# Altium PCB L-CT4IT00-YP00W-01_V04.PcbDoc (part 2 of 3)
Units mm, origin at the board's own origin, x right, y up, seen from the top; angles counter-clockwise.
Board outline 45 x 50 mm, 6 copper layers (Top Layer, GND1, Signal3, Siganl4, GND5, Bottom Layer), stack 1.57 mm thick; 213 components, 129 nets, 723 pads, 573 vias.
Unrouted connection lines stored in the file: 173.
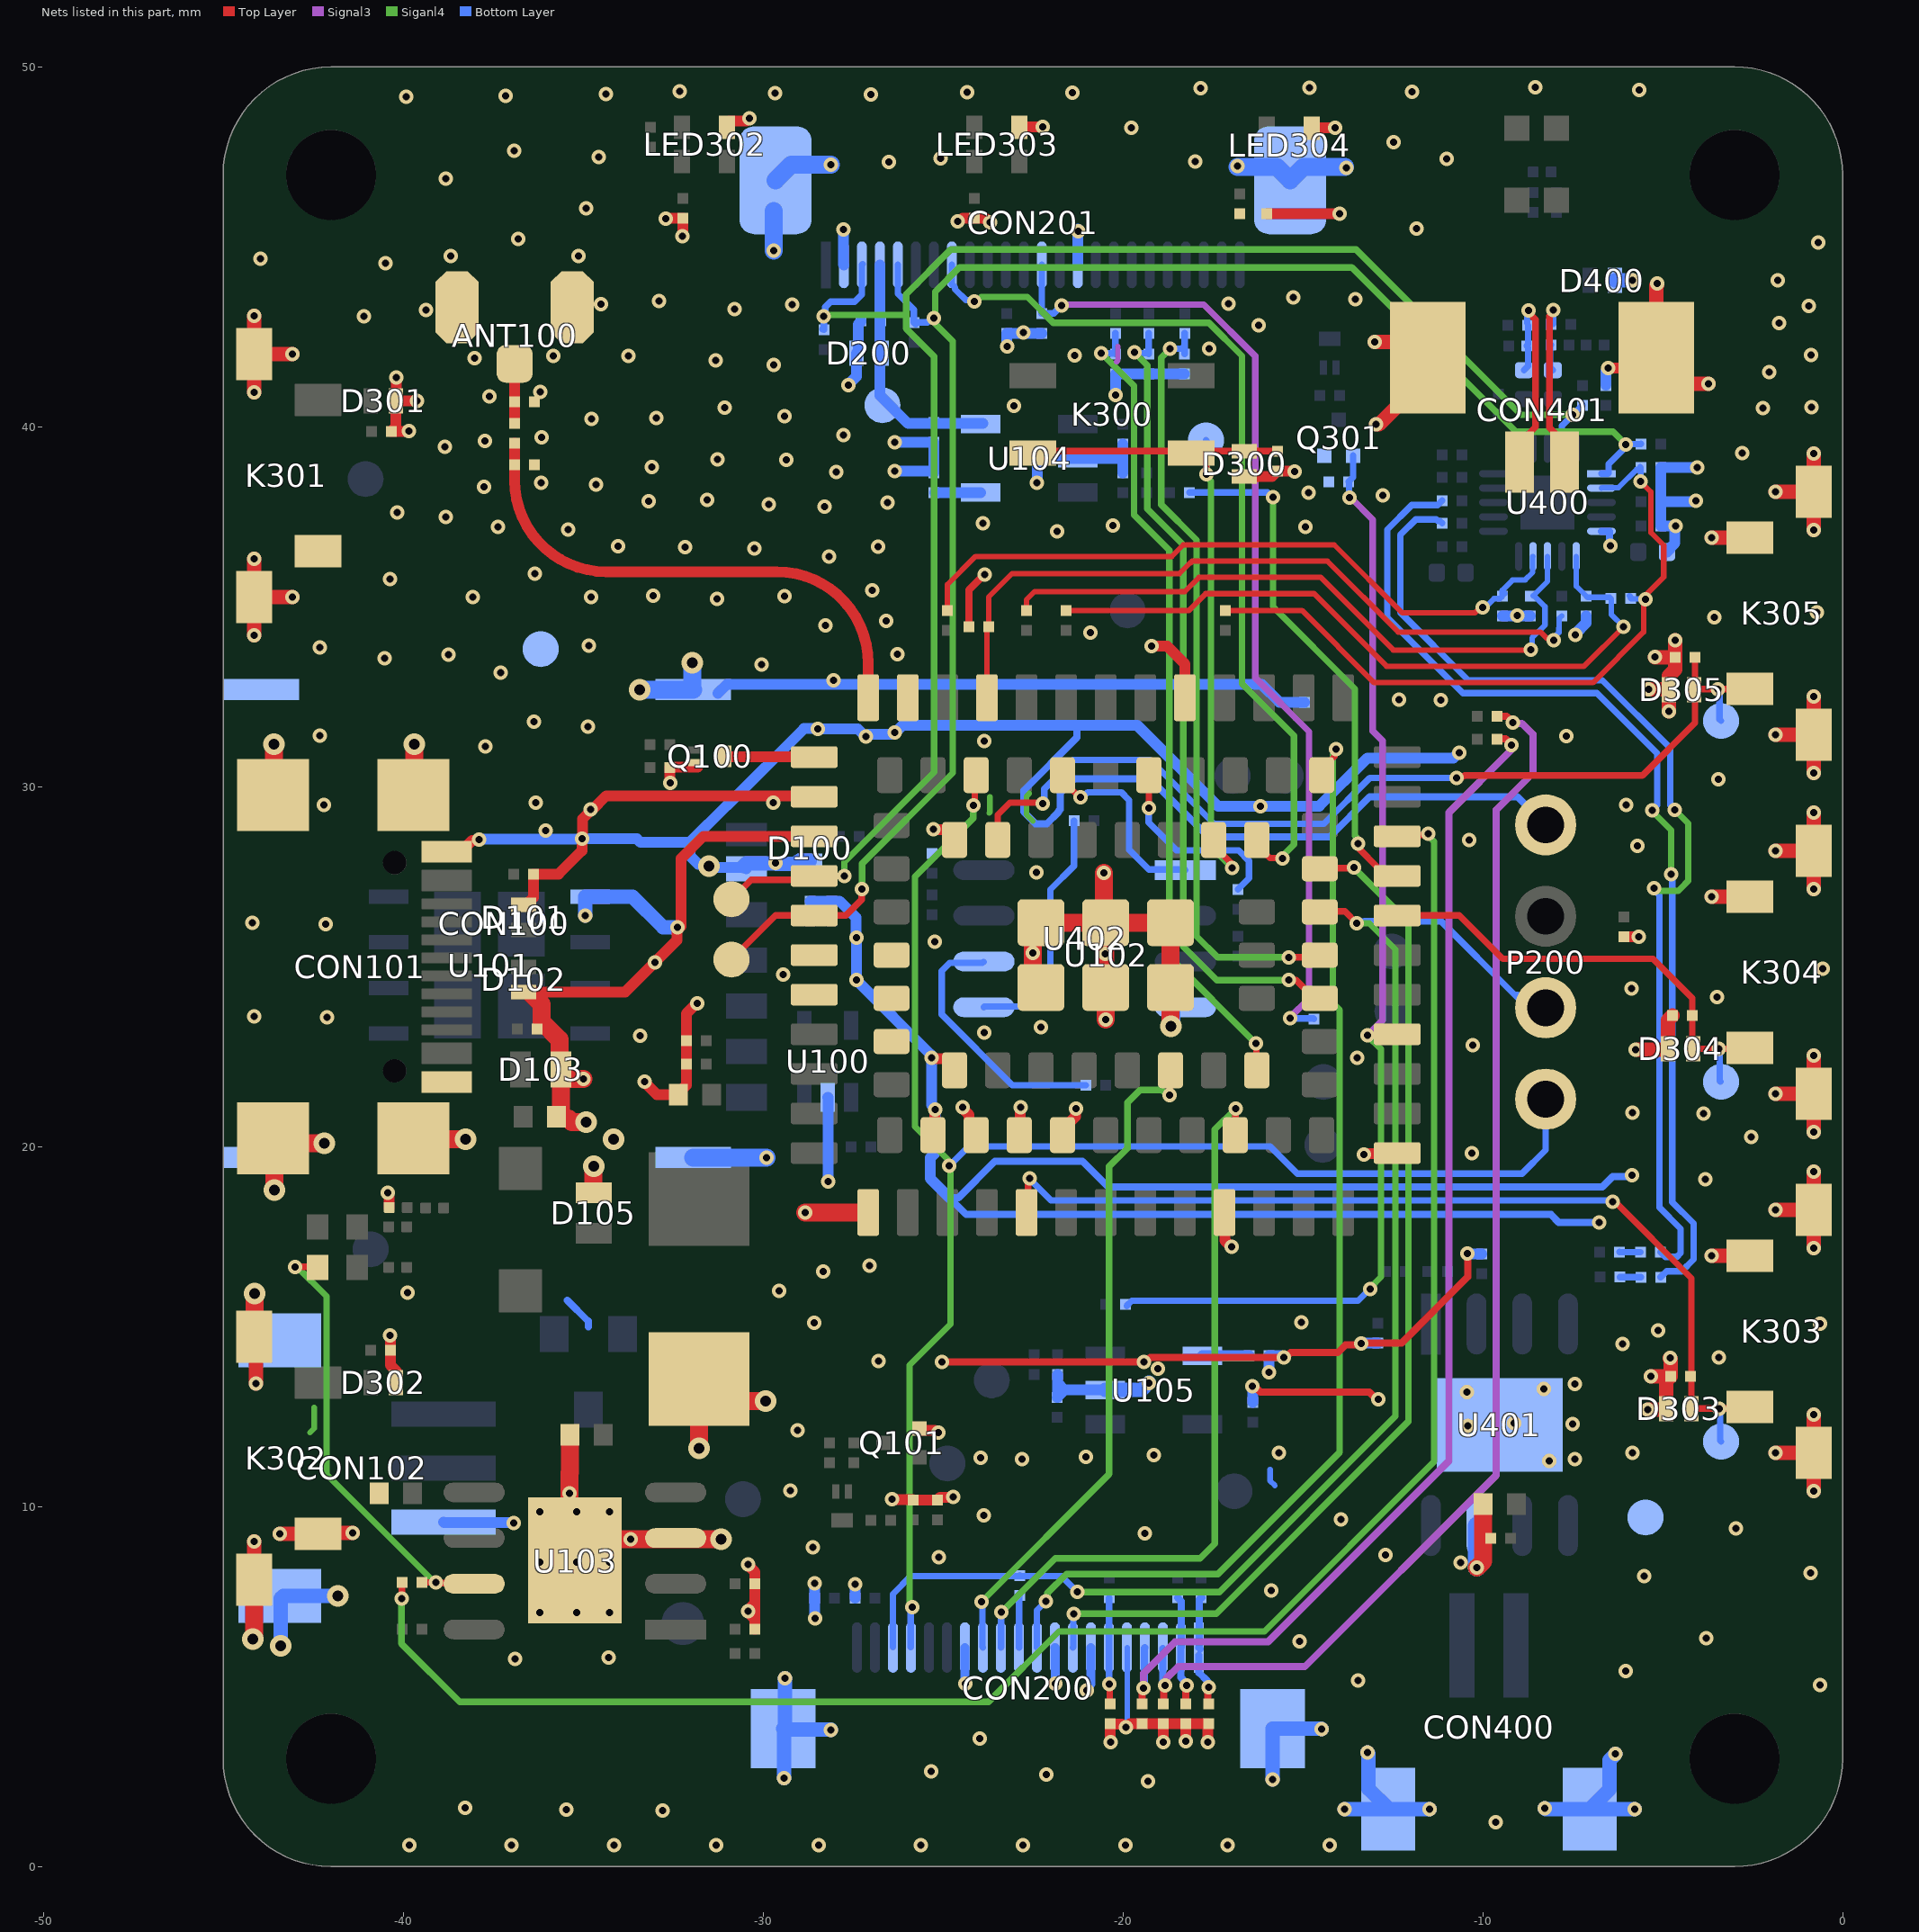
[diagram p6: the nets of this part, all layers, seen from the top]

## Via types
v1: diameter 0.4, hole 0.2, Top Layer to Bottom Layer, tented both sides, 541 vias
v2: diameter 0.6, hole 0.3, Top Layer to Bottom Layer, tented both sides, 32 vias

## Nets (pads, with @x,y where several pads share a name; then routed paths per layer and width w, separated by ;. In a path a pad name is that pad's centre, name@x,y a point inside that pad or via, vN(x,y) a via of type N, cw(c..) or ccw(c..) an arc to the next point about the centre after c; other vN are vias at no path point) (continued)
AUD_N: C406.1 R410.1 | length 29.1
  Siganl4 w0.18: v1(-5.288,29.344) -5.288,29.317 -4.765,28.795 v1(-4.765,27.576)
  Bottom Layer w0.18: R410.1@-11.125,37.95 -11.249,37.826 -11.969,37.826 -12.652,37.143 -12.652,34.702 -10.549,32.599 -6.824,32.599 -5.15,30.925 -5.15,29.481 v1(-5.288,29.344) ; C406.1@-5.054,16.376 -4.889,16.541 -4.469,16.541 -4.14,16.87 -4.14,17.87 -4.731,18.461 -4.731,27.542 v1(-4.765,27.576)
AUD_P: C407.1 R411.1 | length 28.7
  Siganl4 w0.18: v1(-5.232,27.186) -5.153,27.106 -4.57,27.106 -4.491,27.186 -4.489,27.186 -4.288,27.387 -4.288,28.982 v1(-4.662,29.356)
  Bottom Layer w0.18: R411.1@-11.125,37.325 -11.185,37.385 -11.247,37.385 -11.29,37.428 -11.858,37.428 -12.292,36.994 -12.292,34.851 -10.4,32.959 -6.675,32.959 -4.79,31.074 -4.79,29.484 v1(-4.662,29.356) ; v1(-5.232,27.186) -5.232,27.126 -5.091,26.985 -5.091,18.312 -4.5,17.721 -4.5,17.044 -4.605,16.938 -4.927,16.938 C407.1@-5.061,17.072
CAM_MCLK: C208.2 CON201.13 R119.1 | length 27.9
  Signal3 w0.18: v1(-21.698,43.372) -21.673,43.397 -17.751,43.397 -16.318,41.964 -16.318,33.788 -16.32,33.786 -16.32,33.026 -14.827,31.533 -14.827,24.117 v1@-15.354,23.59
  Bottom Layer w0.18: CON201.13@-22.25,44.501 -22.253,44.498 -22.253,43.154 C208.2@-22.256,43.151 -21.92,43.151 v1(-21.698,43.372) ; v1(-15.354,23.574) -15.342,23.562 -14.701,23.562 R119.1@-14.689,23.55
CAM_PWDN: CON201.8 U102.81 | length 25.3
  Top Layer w0.18: U102.81@-16.275,28.525 -16.275,28.383 -15.912,28.02 -15.576,28.02 v1(-15.569,28.013)
  Siganl4 w0.18: v1(-24.125,43.477) -24.066,43.477 -23.937,43.607 -22.648,43.607 -21.933,42.892 -17.607,42.892 -16.687,41.971 -16.687,32.862 -15.245,31.421 -15.245,28.397 -15.569,28.073 v1(-15.569,28.013)
  Bottom Layer w0.18: CON201.8@-24.75,44.501 -24.75,43.964 -24.66,43.874 -24.66,43.821 -24.358,43.519 -24.167,43.519 v1(-24.125,43.477)
CAM_SPI_CLK: C209.2 R202.1 U102.80 | length 22.7
  Top Layer w0.18: v1(-16.304,22.871) -16.29,22.857 -16.29,22.139 U102.80@-16.275,22.125
  Siganl4 w0.18: v1(-20.603,42.052) -19.689,41.138 -19.689,37.553 -18.709,36.573 -18.709,25.276 v1(-16.304,22.871)
  Bottom Layer w0.18: v1(-20.603,42.052) -20.59,42.039 -20.219,42.039 C209.2@-20.206,42.026 R202.1@-20.206,42.601
CAM_SPI_D0: C210.2 R203.1 U102.55 | length 22.5
  Top Layer w0.18: v1@-15.423,24.627 v1(-15.389,24.627) ; v1@-15.347,24.585 v1(-15.389,24.627) ; U102.55@-14.525,24.125 -14.68,24.125 -15.182,24.627 v1(-15.389,24.627)
  Siganl4 w0.18: v1(-19.674,42.064) -19.317,41.707 -19.317,37.719 -18.318,36.72 -18.318,25.556 -17.389,24.627 v1(-15.389,24.627)
  Bottom Layer w0.18: v1(-19.674,42.064) -19.655,42.045 -19.3,42.045 C210.2@-19.281,42.026 R203.1@-19.281,42.601
CAM_SPI_D1: C211.2 R204.1 U102.56 | length 21.5
  Top Layer w0.18: v1(-15.39,25.262) -14.587,25.263 U102.56@-14.525,25.325
  Siganl4 w0.18: v1(-18.682,42.171) -18.931,41.922 -18.931,37.842 -17.947,36.858 -17.947,25.848 -17.361,25.262 v1(-15.39,25.262)
  Bottom Layer w0.18: v1(-18.682,42.171) -18.361,42.17 -18.281,42.25 ; C211.2@-18.281,42.026 -18.281,42.171 -18.281,42.25 ; R204.1@-18.281,42.601 -18.281,42.25
CAM_VDD: C117.2 C213.1 CON201.4 D200.K TP112.1 U104.5 | length 6.8
  Bottom Layer w0.3: CON201.4@-26.75,44.501 -26.75,42.051 -26.75,40.875 -25.965,40.09 -23.95,40.09 U104.5@-23.893,40.09
CHG_LED: LED301.K R102.2 U103.7 | length 12.5
  Top Layer w0.18: v1(-42.997,16.662) -42.387,16.662 LED301.K@-42.375,16.65 ; R102.2@-39.475,7.9 v1(-39.092,7.898) ; v1(-39.092,7.898) -39.072,7.878 -38.045,7.878 U103.7@-38.025,7.858
  Siganl4 w0.18: v1(-42.997,16.662) -42.944,16.662 -42.125,15.843 -42.125,12.896 -42.124,12.895 -42.124,12.033 -42.125,12.032 -42.125,10.898 -39.125,7.898 v1(-39.092,7.898)
CHG_STATE: R102.1 U102.21 | length 52.2
  Top Layer w0.18: v1(-40.043,7.445) -40.034,7.454 -40.034,7.891 R102.1@-40.025,7.9 ; U102.21@-12.375,28.625 -12.343,28.657 -11.542,28.657 v1(-11.509,28.69)
  Siganl4 w0.18: v1(-40.043,7.445) -40.043,6.192 -38.429,4.577 -23.732,4.577 -21.773,6.536 -16.063,6.536 -11.349,11.251 -11.349,28.474 -11.509,28.635 v1(-11.509,28.69)
CHRG_PAD: Q100.D U102.97 | length 2.5
  Top Layer w0.3: Q100.D@-31.075,30.85 -31.063,30.838 -28.588,30.838 U102.97@-28.575,30.825
CODEC_I2S_BCLK: C408.2 R106.2 R405.2 U400.6 | length 19.8
  Top Layer w0.152: R106.2@-21.575,34.9 -18.161,34.9 -17.697,35.364 -14.687,35.364 -12.669,33.346 -7.186,33.346 v1(-6.087,34.445)
  Bottom Layer w0.152: U400.6@-7.4,36.4 -7.4,35.575 C408.2@-7.125,35.3 -7.09,35.265 -6.469,35.265 R405.2@-6.433,35.23 -6.426,35.223 -6.426,34.784 v1(-6.087,34.445)
CODEC_I2S_DIN: C405.2 R406.1 U102.32 | length 20.6
  Top Layer w0.152: U102.32@-23.778,32.478 -23.778,34.397 C405.2@-23.725,34.45 -23.725,35.275 -23.075,35.925 -18.425,35.925 -18.125,36.225 -18.114,36.225 -18.071,36.268 -14.313,36.268 -12.344,34.3 -8.396,34.3 -8.217,34.121 -8.075,34.121 v1(-8.028,34.074)
  Bottom Layer w0.152: v1(-8.028,34.074) -8.028,34.141 -7.882,34.287 -7.882,34.407 -7.874,34.416 -7.874,34.676 R406.1@-7.8,34.75
CODEC_I2S_DOUT: C402.2 R104.2 U400.9 | length 19.4
  Top Layer w0.152: R104.2@-24.875,34.9 -24.875,35.614 -24.089,36.4 -18.638,36.4 -18.318,36.72 -14.125,36.72 -12.24,34.835 -10.211,34.835 -10.065,34.981 v1(-9.998,34.981)
  Bottom Layer w0.152: v1(-9.998,34.981) -9.931,34.981 -9.686,35.226 -9.524,35.226 C402.2@-9.461,35.289 ; C402.2@-9.461,35.27 C402.2@-9.461,35.289 ; C402.2@-9.376,35.374 C402.2@-9.45,35.3 ; U400.9@-8.6,36.4 -8.609,36.391 -8.609,35.958 -8.817,35.75 -8.846,35.75 -8.853,35.744 -9.169,35.744 -9.461,35.452 C402.2@-9.461,35.3 ; C402.2@-9.461,35.289 C402.2@-9.461,35.3 ; C402.2@-9.461,35.289 C402.2@-9.45,35.3 ; C402.2@-9.461,35.3 C402.2@-9.45,35.3
CODEC_I2S_LRCK: C403.2 R105.2 U400.8 | length 18.5
  Top Layer w0.152: R105.2@-22.675,34.9 -22.675,35.2 -22.45,35.425 -18.275,35.425 -17.884,35.816 -14.5,35.816 -12.482,33.798 -8.667,33.798 v1(-8.658,33.807)
  Bottom Layer w0.152: v1(-8.658,33.807) -8.626,33.839 -8.626,34.137 -8.269,34.494 -8.269,35.006 -8.564,35.301 C403.2@-8.591,35.301 ; C403.2@-8.598,35.308 -8.2,35.705 U400.8@-8.2,36.4
CODEC_I2S_MCLK: C409.2 R107.2 R405.1 U400.2 | length 20
  Top Layer w0.152: R107.2@-17.148,34.9 -15.023,34.9 -13.017,32.894 -6.937,32.894 -5.53,34.301 -5.53,35.266 -4.97,35.827 -4.97,36.708 -5.325,37.063 -5.325,38.194 v1(-5.615,38.484)
  Bottom Layer w0.152: U400.2@-6.7,38.3 -6.691,38.309 -6.226,38.309 -5.718,38.817 -5.673,38.817 -5.627,38.863 C409.2@-5.627,38.9 ; R405.1@-5.919,35.304 R405.1@-5.895,35.279 ; R405.1@-5.845,35.23 R405.1@-5.895,35.279 ; v1(-5.615,38.484) -5.607,38.491 -5.607,38.868 C409.2@-5.6,38.875 ; v1(-5.474,35.211) -5.483,35.22 -5.874,35.22 R405.1@-5.883,35.23 -5.895,35.241 R405.1@-5.895,35.279
FLASH_CLK: R114.2 U402.6 | length 7.3
  Bottom Layer w0.18: U402.6@-23.869,25.136 -23.898,25.107 -24.808,25.107 -25.032,24.883 -25.032,23.675 -23.068,21.711 R114.2@-21.023,21.711
FLASH_CS: U102.64 U402.1 | length 5.5
  Top Layer w0.18: U102.64@-21.675,30.325 -21.675,30.183 -21.199,29.707 v1(-21.176,29.707)
  Bottom Layer w0.18: v1(-21.176,29.707) -21.117,29.707 -20.975,29.849 -20.047,29.849 -19.825,29.627 -19.825,28.253 -19.275,27.702 -18.277,27.702 U402.1@-18.26,27.685
FLASH_MISO: R417.1 U102.62 | length 5.4
  Top Layer w0.18: v1(-19.282,29.413) -19.278,29.416 -19.278,30.265 U102.62@-19.282,30.268
  Bottom Layer w0.18: v1(-19.282,29.413) -19.282,29.007 -18.505,28.23 -16.784,28.23 -16.492,27.938 -16.492,27.458 R417.1@-16.8,27.15
FLASH_MOSI: R123.2 U402.5 | length 7
  Bottom Layer w0.18: U402.5@-23.86,23.875 -23.843,23.892 -22.58,23.892 -22.01,24.462 -22.01,27.148 -21.357,27.801 R123.2@-21.357,29.06
GND: ANT100.2 ANT100.3 C100.1 C101.1 C102.2 C103.1 C104.1 C105.1 C106.1 C107.1 C109.1 C110.1 C111.1 C112.1 C113.1 C114.1 C115.1 C116.1 C117.1 C118.1 C200.1 C201.2 C202.2 C203.1 C204.1 C205.1 C206.1 C207.1 C208.1 C209.1 C210.1 C211.1 C212.2 C213.2 C300.1 C301.1 C302.1 C303.1 C304.1 C305.1 C306.2 C307.2 C308.2 C309.2 C400.1 C401.2 C402.1 C403.1 C404.2 C405.1 C408.1 C409.1 C410.1 C411.2 C412.1 C423.1 CON100.0@-31.942,19.7 CON100.0@-31.942,32.7 CON100.0@-43.942,19.7 CON100.0@-43.942,32.7 CON100.5 CON101.0 CON101.A1B12 CON101.B1A12 CON102.0 CON102.1 CON200.0 CON200.5 CON200.7 CON200.9 CON200.14 CON201.0 CON201.2 CON201.15 CON400.0 CON401.0 D100.A D101.A D102.A D103.A D105.A D200.A D300.A D301.A D302.A D303.A D304.A D305.A D400.A K301.1 K301.2 K301.4 K302.1 K302.2 K302.4 K303.1 K303.2 K303.4 K304.1 K304.2 K304.4 K305.1 K305.2 K305.4 LED302.1 LED303.1 LED304.1 P200.4 Q100.S Q101.E Q301.S R108.2 R109.2 R110.2 R112.2 R113.1 R124.1 R126.1 R129.1 R130.1 R302.1 R306.1 R402.1 R409.2 TP307.1 TP308.1 U100.2 U101.1 U102.1 U102.10 U102.27 U102.34 U102.36 U102.37 U102.40 U102.41 U102.45 U102.46 U102.47 U102.48 U102.70 U102.71 U102.72 U102.73 U102.88 U102.89 U102.90 U102.91 U102.92 U102.93 U102.94 U102.95 U103.0 U103.3 U104.2 U105.2 U400.5 U401.0 U401.7 U402.4 | length 371.3
  Top Layer w0.2: v1(-25.022,14.022) -25.02,14.019 -19.42,14.019 v1(-19.417,14.017) -19.363,14.017 -19.236,14.144 -15.467,14.144 -15.332,14.279 -14.023,14.279 -13.808,14.494 -13.421,14.494 -13.366,14.548 -12.252,14.548 -10.417,16.383 -10.417,17.019 v1(-10.427,17.029) ; C405.1@-24.275,34.45 -24.275,35.474 v1@-23.825,35.924 ; v1(-16.395,13.348) -16.341,13.348 -16.173,13.18 -13.148,13.18 -12.951,12.983 v1(-12.897,12.983)
  Top Layer w0.3: v1(-40.431,18.717) -40.412,18.698 -40.412,18.627 -40.383,18.598 R302.1@-40.383,18.312 ; v1(-40.361,14.761) -40.35,14.75 -40.35,13.928 -40.171,13.749 D302.A@-40.171,13.478 ; D302.A@-40.25,13.5 D302.A@-40.2,13.45 ; v1(-40.188,41.373) -40.194,41.367 -40.194,40.731 D301.A@-40.2,40.725 ; v1(-39.834,39.887) -39.847,39.875 C301.1@-40.325,39.875 -40.2,40 D301.A@-40.2,40.725 ; v1(-39.614,40.724) D301.A@-40.2,40.725 ; CON101.A1B12@-38.787,28.2 -38.387,28.2 -38.078,28.509 -37.905,28.509 v1(-37.886,28.529) ; D102.A@-36.65,24.3 -33.825,24.3 -32.394,25.731 -32.394,26.052 v1@-32.328,26.117 ; D101.A@-36.65,26.725 -36.5,26.725 D101.A@-36.45,26.775 ; D101.A@-36.575,26.725 -36.378,26.922 R108.2@-36.378,27.572 ; R108.2@-36.375,27.575 -35.682,27.575 -35.03,28.227 v1(-35.03,28.555) ; v1@-35.011,28.574 -35.011,29.11 -34.779,29.342 -34.762,29.342 -34.354,29.75 -28.6,29.75 U102.36@-28.575,29.725 ; v1(-33.283,21.808) -33.283,21.783 -32.95,21.45 C103.1@-32.35,21.45 ; v1(-32.701,45.78) -32.682,45.799 -32.226,45.799 -32.226,45.301 v1(-32.232,45.295) ; v1(-32.577,30.11) -32.592,30.126 R113.1@-32.592,30.527 -32.57,30.549 -31.815,30.549 ; C103.1@-32.339,21.45 -32.339,21.499 -32.125,21.712 C104.1@-32.125,22.3 C105.1@-32.125,22.95 -32.125,23.7 v1@-31.875,23.95 ; v1@-32.275,26.125 -32.275,28.005 -31.655,28.625 U102.37@-28.575,28.625 ; LED302.1@-31,48.325 -31,48.425 -30.925,48.5 -30.467,48.5 -30.398,48.569 v1(-30.371,48.569) ; v1(-30.415,7.099) -30.415,7.072 -30.225,6.882 ; v1(-30.413,8.4) -30.413,8.373 -30.225,8.185 R110.2@-30.225,7.861 -30.225,7.316 ; v1@-30.396,7.118 -30.396,7.145 -30.225,7.316 ; R112.2@-30.225,6.6 -30.225,6.882 ; v1(-26.417,10.209) -26.398,10.19 -25.83,10.19 C112.1@-25.819,10.18 R126.1@-25.152,10.18 -25.074,10.257 -24.736,10.257 v1(-24.717,10.277) ; Q101.E@-25.65,12.175 -25.6,12.125 -25.224,12.125 -25.158,12.059 v1(-25.131,12.059) ; v1(-25.308,22.471) -25.289,22.452 -24.875,22.452 -24.675,22.252 U102.73@-24.675,22.125 ; U102.45@-25.275,20.325 -25.228,20.372 -25.228,21.01 v1(-25.209,21.03) ; v1(-25.268,28.821) -25.249,28.802 -24.875,28.802 -24.675,28.602 U102.88@-24.675,28.525 ; v1@-24.568,45.682 -24.45,45.8 C309.2@-24.125,45.8 ; v1(-24.455,21.094) -24.455,21.067 -24.275,20.887 -24.275,20.525 U102.46@-24.075,20.325 ; C309.2@-24.121,45.796 -23.827,45.796 -23.713,45.682 v1(-23.686,45.682) ; U102.47@-22.875,20.325 -22.852,20.348 -22.852,21.076 v1(-22.833,21.095) ; LED303.1@-22.875,48.325 -22.882,48.332 v1@-22.259,48.332 ; U102.48@-21.675,20.325 -21.675,20.475 -21.318,20.832 -21.318,21.042 v1(-21.299,21.061) ; v1@-20.345,3.457 C203.1@-20.345,3.941 ; C203.1@-20.345,3.958 -20.023,3.958 -19.94,3.876 -19.886,3.876 -19.795,3.966 C206.1@-18.252,3.966 ; v1(-19.201,33.907) -18.769,33.907 -18.275,33.413 U102.27@-18.275,32.475 ; v1@-18.873,3.456 C205.1@-18.873,3.941 ; v1(-18.25,3.479) -18.252,3.481 C206.1@-18.252,3.966 ; C207.1@-17.649,3.966 C206.1@-18.252,3.966 ; v1@-17.644,3.457 C207.1@-17.644,3.941 ; U102.10@-17.168,18.195 -17.168,17.395 v1@-16.989,17.216 ; D300.A@-16.625,38.625 -15.85,38.625 C300.1@-15.7,38.775 v1@-15.194,38.775 ; C308.2@-15.975,45.925 v1(-13.975,45.925) ; LED304.1@-14.75,48.3 -14.757,48.307 v1@-14.134,48.307 ; v1(-13.3,19.789) -13.282,19.807 -12.393,19.807 U102.95@-12.375,19.825 ; CON401.0@-12.135,41.315 CON401.0@-11.525,41.925 CON401.0@-11.952,42.352 ; v1(-6.512,41.627) -5.473,41.627 CON401.0@-5.175,41.925 ; C200.1@-6.075,25.832 v1@-5.664,25.832 ; -30.225,6.882 -30.225,7.316
  Top Layer w0.4: K302.2@-44.138,7.975 v1(-44.137,9.038) ; v1(-44.138,34.212) K301.2@-44.138,35.275 ; v1(-44.137,36.338) K301.2@-44.138,35.275 ; v1(-44.138,40.962) K301.1@-44.138,42.025 ; v1(-44.137,43.088) K301.1@-44.138,42.025 ; v1(-44.091,13.425) K302.1@-44.09,14.488 ; v1(-43.426,9.25) K302.4@-42.363,9.25 -42.345,9.268 v1(-41.401,9.268) ; v1(-43.074,35.275) K301.2@-44.138,35.275 ; v1(-43.074,42.025) K301.1@-44.138,42.025 ; v1(-13.005,42.352) CON401.0@-11.952,42.352 ; v1(-12.966,40.067) -12.883,40.067 -12.135,40.815 CON401.0@-12.135,41.315 ; v1@-5.7,22.7 -4.85,22.7 D304.A@-4.85,22.725 -4.85,23.525 C304.1@-4.725,23.65 ; v1(-5.408,12.697) -4.9,12.697 D303.A@-4.9,12.725 -4.9,13.5 C303.1@-4.784,13.616 ; v1(-5.388,32.711) D305.A@-4.825,32.711 ; v1(-5.322,13.616) C303.1@-4.784,13.616 ; v1@-5.21,33.6 C305.1@-4.65,33.6 ; v1@-5.15,43.95 -5.175,43.925 CON401.0@-5.175,41.925 -4.447,41.197 v1(-3.727,41.197) ; v1(-4.828,32.093) -4.825,32.096 D305.A@-4.825,32.7 D305.A@-4.825,32.711 ; v1@-4.8,14.125 -4.775,14.1 C303.1@-4.775,13.625 C303.1@-4.784,13.616 ; v1(-4.655,34.073) -4.65,34.068 C305.1@-4.65,33.6 ; v1(-3.638,16.975) K303.4@-2.575,16.975 ; v1(-3.638,26.95) K304.4@-2.575,26.95 ; v1(-3.638,36.925) K305.4@-2.575,36.925 ; v1(-1.863,11.5) K303.1@-0.8,11.5 ; v1(-1.863,18.25) K303.2@-0.8,18.25 ; v1(-1.863,21.475) K304.1@-0.8,21.475 ; v1(-1.863,28.225) K304.2@-0.8,28.225 ; v1(-1.863,31.45) K305.1@-0.8,31.45 ; v1(-1.863,38.2) K305.2@-0.8,38.2 ; v1(-0.8,10.437) K303.1@-0.8,11.5 ; v1(-0.8,12.563) K303.1@-0.8,11.5 ; v1(-0.8,17.187) K303.2@-0.8,18.25 ; v1(-0.8,19.313) K303.2@-0.8,18.25 ; v1(-0.8,20.412) K304.1@-0.8,21.475 ; v1(-0.8,22.538) K304.1@-0.8,21.475 ; v1(-0.8,27.162) K304.2@-0.8,28.225 ; v1(-0.8,29.288) K304.2@-0.8,28.225 ; v1(-0.8,30.387) K305.1@-0.8,31.45 ; v1(-0.8,32.513) K305.1@-0.8,31.45 ; v1(-0.8,37.137) K305.2@-0.8,38.2 ; v1(-0.8,39.263) K305.2@-0.8,38.2 ; D305.A@-4.825,32.711 -4.825,33.087 -4.65,33.262 C305.1@-4.65,33.6
  Top Layer w0.5: v2(-44.178,6.322) -44.178,6.35 -44.138,6.39 K302.2@-44.138,7.975 ; v2(-44.128,15.918) -44.128,14.526 K302.1@-44.09,14.488 ; CON101.0@-43.619,20.053 -43.582,20.091 v2(-42.189,20.091) ; CON101.0@-43.612,20.23 -43.575,20.192 v2(-43.575,18.8) ; CON101.0@-43.612,29.77 -43.588,29.795 v2(-43.588,31.184) ; CON101.0@-39.712,29.77 -39.688,29.795 v2(-39.688,31.184) ; CON101.0@-39.696,20.172 -39.658,20.21 v2(-38.266,20.21) ; D102.A@-36.444,24.249 -36.15,23.954 -36.15,23.475 -35.655,22.98 -35.655,22.19 D103.A@-35.615,22.15 D103.A@-35.615,21.94 ; R124.1@-35.743,20.828 -35.743,20.866 -35.615,20.993 D103.A@-35.615,21.94 ; R124.1@-35.73,20.878 -35.73,20.778 -35.4,20.778 -35.31,20.689 v2(-34.914,20.689) ; C106.1@-35.367,12.001 -35.367,10.951 -35.375,10.944 -35.375,9.966 -35.211,9.802 -35.211,8.489 -35.191,8.469 -35.178,8.469 -35.178,8.549 -34.634,9.093 v2(-31.168,9.093) ; v1(-34.988,21.884) -35.349,21.884 -35.365,21.9 -35.575,21.9 D103.A@-35.615,21.94 ; v2@-34.708,19.441 -34.708,18.724 D105.A@-34.702,18.718 ; v2@-31.775,11.625 C102.2@-31.775,13.55 -31.164,12.939 v2(-29.925,12.939) ; v1@-28.829,18.175 U102.1@-27.075,18.175 ; U102.89@-22.275,24.425 -22.504,24.654 -22.504,25.996 U102.94@-22.275,26.225 U102.93@-20.507,26.225 ; v1(-20.525,27.604) -20.525,26.244 U102.93@-20.507,26.225 ; v1(-20.471,23.529) -20.471,24.421 -20.491,24.441 v1(-20.491,25.357) U102.93@-20.491,26.209 ; v2@-18.675,23.35 U102.91@-18.675,24.425 U102.92@-18.675,26.225 U102.93@-20.475,26.225 ; v1(-10.163,8.305) -9.988,8.48 C411.2@-9.988,10.075 ; U102.93@-20.507,26.225 U102.93@-20.491,26.209 ; U102.93@-20.507,26.225 U102.93@-20.475,26.225 ; U102.93@-20.491,26.209 U102.93@-20.475,26.225
  Signal3 w0.152: -20.168,41.809 -20.137,41.84 -20.137,42.23
  Siganl4 w0.152: -42.586,12.061 -42.47,12.177 -42.47,12.751 -42.474,12.756 ; -23.717,29.273 -23.694,29.297 -23.694,29.719 ; -22.596,29.814 -22.596,29.811 -22.678,29.728 -22.678,29.228 -22.5,29.05
  Bottom Layer w0.152: v1(-19.913,3.876) -19.881,3.908 CON200.5@-19.881,6.083 ; -15.906,11.037 -15.906,10.719 -15.773,10.585
  Bottom Layer w0.2: -35.436,15.732 -34.856,15.152 -34.856,15 ; -21.275,31.707 -21.275,31.371 -22.755,29.891 -22.755,29.305 -22.426,28.976 -22.107,28.976 -21.787,29.296 -21.787,29.326 -21.742,29.37 -21.742,29.82 -21.343,30.219 -19.248,30.219 -18.754,29.725 -18.736,29.725 -17.613,28.602 -14.258,28.602 -13.135,29.725 -9.035,29.725 P200.4@-8.25,28.94 ; v1(-6.76,17.895) -7.885,17.895 -8.104,18.115 -24.347,18.115 -24.817,18.584 -24.566,18.584 -23.55,19.6 -21.125,19.6 -20.406,18.881 -6.675,18.881 -6.388,19.168 -5.891,19.168 v1(-5.853,19.206) ; U400.5@-6.7,37.1 -6.473,37.1 -6.473,36.727 v1(-6.446,36.7)
  Bottom Layer w0.25: v1@-24.383,5.084 CON200.14@-24.383,6.085 ; CON200.9@-21.885,6.088 -21.881,6.083 -21.881,5.081 v1(-21.876,5.077) ; v1@-21.05,4.9 -20.885,5.065 CON200.7@-20.885,6.088
  Bottom Layer w0.3: CON102.1@-38.875,9.575 -38.862,9.562 -36.933,9.562 v1(-36.92,9.549) ; v1(-37.886,28.529) -37.872,28.542 -35.07,28.542 -35.057,28.555 -33.505,28.555 -33.406,28.456 -32.028,28.456 -32.024,28.46 ; CON100.0@-31.25,32.6 -31.007,32.843 -16.138,32.843 -15.644,32.35 C109.1@-14.95,32.35 ; CON100.5@-30.457,27.72 -30.538,27.8 -30.583,27.755 -31.45,27.755 -31.542,27.847 -31.799,27.847 -32.024,28.073 -32.024,28.46 ; C101.1@-28.688,26.825 -27.871,26.825 -27.416,26.37 -27.416,25.848 -27.375,25.807 -27.399,25.783 -27.399,24.625 -25.328,22.553 -25.328,22.452 -25.341,22.438 -25.322,22.438 -25.308,22.425 -25.308,21.156 -25.209,21.057 -25.209,19.833 -25.35,19.692 -25.35,19.117 -24.817,18.584 ; v1(-28.563,7.872) C201.2@-28.562,7.454 -28.562,6.903 v1(-28.556,6.896) ; v1@-28.489,31.615 -28.86,31.615 -30.975,29.5 -30.984,29.5 -32.024,28.46 ; v1(-28.477,31.604) -27.361,31.604 -27.155,31.398 -27.108,31.398 -27.051,31.455 -26.424,31.455 -26.37,31.509 -26.315,31.509 -26.117,31.707 -21.275,31.707 -19.601,31.707 -17.354,29.46 v1(-16.173,29.46) -14.54,29.46 -13.2,30.8 -10.812,30.8 v1@-10.648,30.964 ; U100.2@-28.2,21.375 -28.192,21.367 -28.192,19.039 v1(-28.185,19.031) ; v1(-27.764,45.479) -27.757,45.472 -27.757,44.508 CON201.2@-27.75,44.501 ; v1@-27.625,41.175 -27.406,41.394 D200.A@-27.406,42.051 -27.356,42.101 -27.356,42.851 -27.281,42.926 C213.2@-27.281,42.951 ; C202.2@-27.437,7.454 -27.437,7.849 v1(-27.436,7.85) ; v1@-26.325,38.775 C115.1@-25.25,38.775 ; v1@-26.325,39.575 C117.1@-25.25,39.575 C115.1@-25.25,38.725 ; C212.2@-23.231,42.601 C208.1@-22.256,42.601 ; C212.2@-23.231,42.601 -23.23,42.249 v1(-23.211,42.23) ; v1(-22.389,38.441) -22.369,38.46 -22.369,38.881 -22.125,39.125 U104.2@-21.25,39.125 -20.071,39.125 -20,39.054 ; C114.1@-21.821,13.035 C114.1@-21.818,13.038 ; R130.1@-21.818,13.666 -21.818,13.445 ; CON201.15@-21.25,44.501 v1@-21.25,45.5 ; U105.2@-20.493,13.241 -21.615,13.241 ; v1@-20.2,40.875 -20.206,40.881 C209.1@-20.206,41.476 C210.1@-19.281,41.476 C211.1@-18.282,41.476 ; R129.1@-20,38.725 -20,39.054 ; C113.1@-20,39.525 -20,39.054 ; v1(-16.395,13.348) -16.393,13.346 C118.1@-16.393,12.891 ; v1(-15.943,13.731) C116.1@-15.943,14.191 -15.595,14.191 -15.548,14.144 v1(-15.521,14.144) ; v1(-13.377,14.532) -13.369,14.54 R402.1@-12.917,14.54 ; v1(-10.427,17.029) -10.423,17.024 C410.1@-10.026,17.024 ; U401.7@-10.17,9.475 U401.7@-10.166,9.471 ; v1@-10.166,8.309 v1(-10.163,8.305) ; C402.1@-9.45,34.75 C403.1@-8.675,34.75 ; v1(-7.426,34.219) -7.426,34.246 -7.125,34.547 C408.1@-7.125,34.75 ; R409.2@-6.569,41.156 -6.569,41.542 -6.512,41.6 v1(-6.512,41.627) ; C404.2@-5.05,37.925 -4.125,37.925 v1@-4.1,37.95 ; C400.1@-4.875,36.525 -4.8,36.6 -4.8,36.625 -4.66,36.765 -4.66,37.227 v1(-4.64,37.246) -4.645,37.25 C401.2@-5.05,37.25 C409.1@-5.05,38.875 -4.051,38.875 v1(-4.041,38.866) ; v1(-2.037,41.521) v1@-2.018,41.54 ; C114.1@-21.818,13.038 -21.818,13.445 ; C114.1@-21.818,13.038 -21.615,13.241 ; -21.818,13.445 -21.615,13.241
  Bottom Layer w0.4: v2@-43.384,6.176 -43.401,6.193 -43.401,7.449 -43.324,7.526 v2(-41.818,7.526) ; v1(-34.942,26.421) -34.942,26.95 -34.825,26.95 U101.1@-34.358,26.95 ; U101.1@-34.357,26.949 -33.628,26.949 -32.776,26.098 v1(-32.375,26.098) ; CON100.5@-30.538,27.8 -30.468,27.87 -29.665,27.87 v1(-29.652,27.883) -29.622,27.853 -29.091,27.853 -28.994,27.95 D100.A@-28.7,27.95 ; v1(-29.407,2.454) CON200.0@-29.407,3.81 ; v1(-29.393,5.237) -29.393,3.88 CON200.0@-29.435,3.837 CON200.0@-29.407,3.81 ; v1(-28.11,3.802) -28.119,3.81 CON200.0@-29.407,3.81 ; U105.2@-20.493,13.241 -19.484,13.241 v1@-19.275,13.45 ; v1(-15.842,2.418) -15.842,3.831 CON200.0@-15.835,3.837 -14.494,3.837 v1(-14.474,3.818) ; v1(-13.843,1.597) -13.841,1.6 CON400.0@-12.625,1.6 ; v1(-13.205,3.167) -13.175,3.137 -13.175,2.16 -12.612,1.597 v1(-11.47,1.597) ; v1(-8.271,1.626) -8.246,1.6 -5.777,1.6 v1(-5.775,1.597) ; CON400.0@-7.018,1.607 -6.475,2.15 -6.475,2.961 v1(-6.308,3.128) ; D400.A@-6.329,44.068 -6.329,44.073 v1(-5.836,44.073)
  Bottom Layer w0.5: v2(-33.43,32.7) CON100.0@-31.942,32.7 ; v2(-31.963,33.441) -31.963,32.72 CON100.0@-31.942,32.7 ; CON100.0@-31.942,19.7 -29.915,19.7 v1(-29.906,19.691) ; v1(-29.7,44.889) CON201.0@-29.7,46 ; CON201.0@-29.65,46.851 -29.218,47.283 v1(-28.107,47.283) ; v2(-18.667,23.34) -18.648,23.359 U402.4@-18.648,23.888 ; v1@-16.819,47.225 -15.724,47.225 CON201.0@-15.35,46.851 -14.976,47.225 v1@-13.825,47.225 ; v1@-10.166,8.309 U401.7@-10.166,9.471
  other v1: -39.824,0.594 -36.982,0.594 -34.14,0.594 -31.298,0.594 -28.455,0.594 -25.613,0.594 -22.771,0.594 -19.929,0.594 -17.087,0.594 -14.244,0.594 -9.641,1.228 -32.786,1.555 -35.462,1.588 -38.27,1.628 -19.3,2.368 -22.125,2.555 -25.327,2.642 -20.343,3.454 -18.871,3.454 -17.641,3.454 -23.975,3.555 -21.002,4.894 -0.624,5.043 -24.378,5.079 -13.467,5.168 -6.029,5.431 -36.892,5.773 -34.29,5.811 -15.082,6.254 -3.787,6.345 -36.201,7.056 -35.178,7.056 -34.264,7.056 -15.875,7.675 -5.512,8.07 -0.882,8.164 -10.609,8.442 -36.201,8.457 -35.178,8.457 -34.264,8.457 -25.113,8.592 -12.707,8.659 -28.608,8.867 -33.672,9.09 -19.393,9.256 -2.962,9.395 -13.932,9.649 -23.869,9.761 -36.201,9.859 -35.178,9.859 -34.264,9.859 -35.375,10.375 -29.234,10.448 -8.156,11.264 -22.805,11.324 -7.439,11.325 -23.954,11.358 -21.031,11.385 -19.143,11.43 -15.661,11.495 -5.837,11.495 -29.041,12.115 -10.411,12.246 -7.503,12.292 -9.125,12.325 -10.441,13.185 -8.305,13.273 -7.439,13.409 -19.273,13.436 -19.029,13.837 -26.792,14.045 -4.791,14.138 -3.437,14.145 -6.112,14.52 -5.125,14.9 -0.624,15.086 -28.582,15.103 -15.039,15.125 -39.875,15.943 -29.55,16.001 -28.325,16.53 -27.034,16.69 -16.972,17.216 -28.83,18.174 -3.812,19.095 -10.3,19.825 -2.537,20.27 -3.862,20.92 -5.837,20.945 -13.49,22.468 -5.746,22.697 -10.275,22.825 -33.414,23.084 -23.85,23.175 -22.273,23.324 -42.113,23.6 -44.143,23.623 -31.82,23.984 -3.485,24.157 -5.862,24.397 -27.402,24.632 -29.438,24.779 -0.553,24.942 -33,25.125 -22.504,25.377 -25.228,25.699 -27.397,25.807 -5.663,25.833 -42.15,26.185 -44.192,26.223 -22.4,27.625 -5.696,28.36 -10.375,28.525 -36.032,28.781 -34.784,29.364 -42.201,29.497 -6.007,29.5 -36.316,29.556 -29.71,29.556 -3.449,30.206 -10.645,30.941 -37.712,31.12 -23.852,31.272 -27.135,31.398 -7.672,31.407 -42.312,31.42 -26.342,31.509 -34.862,31.67 -36.365,31.808 -11.157,32.404 -12.319,32.427 -28.04,32.955 -37.287,33.17 -30.037,33.395 -40.512,33.57 -5.21,33.602 -38.737,33.67 -26.262,33.68 -42.312,33.87 -34.837,33.92 -20.903,34.282 -28.263,34.479 -26.58,34.609 -3.558,34.712 -9.034,34.756 -0.718,34.845 -31.27,35.22 -38.062,35.27 -34.781,35.276 -29.396,35.29 -33.046,35.304 -26.963,35.458 -40.362,35.77 -23.844,35.9 -36.333,35.919 -28.165,36.395 -30.235,36.619 -32.165,36.661 -34.025,36.689 -26.807,36.673 -21.825,37.1 -35.41,37.15 -37.368,37.22 -14.927,37.22 -20.276,37.258 -23.891,37.32 -38.812,37.495 -40.162,37.62 -28.283,37.777 -29.837,37.845 -26.541,37.896 -33.175,37.935 -4.075,37.94 -31.549,37.975 -12.775,38.1 -14.843,38.172 -37.746,38.339 -34.637,38.395 -36.165,38.451 -27.962,38.745 -26.339,38.768 -15.22,38.76 -33.086,38.883 -31.259,39.097 -29.351,39.082 -2.789,39.268 -38.837,39.445 -26.339,39.568 -37.732,39.612 -36.151,39.71 -27.759,39.774 -34.762,40.22 -32.962,40.245 -29.4,40.3 -31.061,40.529 -2.215,40.527 -0.861,40.541 -23.022,40.582 -37.606,40.842 -20.202,40.882 -36.193,40.968 -27.62,41.159 -29.7,41.715 -31.312,41.845 -38.019,41.908 -33.737,41.97 -35.831,41.975 -21.333,41.983 -0.875,42 -17.605,42.173 -22.76,42.616 -16.225,42.821 -1.768,42.879 -41.087,43.07 -39.368,43.248 -30.787,43.27 -0.933,43.363 -29.192,43.394 -34.5,43.411 -17.06,43.421 -32.887,43.495 -13.542,43.54 -15.262,43.599 -5.153,43.979 -1.801,44.07 -40.487,44.545 -43.962,44.67 -38.674,44.751 -35.127,44.751 -0.674,45.119 -36.804,45.215 -21.236,45.438 -11.836,45.507 -24.593,45.708 -34.912,46.07 -38.812,46.895 -13.782,47.197 -16.819,47.247 -26.504,47.361 -17.986,47.373 -10.998,47.449 -25.063,47.464 -34.562,47.495 -36.912,47.67 -12.48,47.912 -19.757,48.312 -14.103,48.308 -22.228,48.333 -39.912,49.17 -37.15,49.2 -26.997,49.233 -34.362,49.245 -29.662,49.27 -21.406,49.28 -24.328,49.294 -11.961,49.309 -32.312,49.32 -5.656,49.352 -17.835,49.409 -14.812,49.42 -8.535,49.438
  other v2: -43.401,6.13 -31.777,11.617 -34.7,19.461 -34.149,20.21 -31.495,27.79
I2C0_SCL: CON201.5 R201.1 R404.1 TP102.1 U102.39 U400.1 | length 48.1
  Top Layer w0.18: TP102.1@-30.875,25.2 -29.65,26.425 U102.39@-28.575,26.425 -27.693,26.425 -27.257,26.861 -27.257,27.129 v1@-27.239,27.147
  Siganl4 w0.18: v1(-27.245,27.154) -27.245,27.864 -24.726,30.383 -24.726,42.376 v1@-25.325,42.975 ; v1(-25.255,43.017) -25.213,43.059 -25.213,43.754 -24.542,44.425 -13.635,44.425 -9.075,39.866 -6.378,39.866 v1(-6.024,39.512)
  Bottom Layer w0.18: CON201.5@-26.25,44.501 -26.25,43.699 -25.806,43.254 R201.1@-25.806,42.901 ; R201.1@-25.755,42.85 R201.1@-25.806,42.901 ; v1(-25.255,43.017) -25.314,43.017 -25.431,42.901 R201.1@-25.806,42.901 ; U400.1@-6.7,38.7 -6.51,38.7 -6.5,38.71 -6.5,38.965 -6.066,39.399 -6.066,39.47 v1(-6.024,39.512) -6.017,39.518 -5.607,39.518 R404.1@-5.6,39.525
I2C0_SDA: CON201.3 R200.1 R403.1 TP103.1 U102.38 U400.19 | length 48.4
  Top Layer w0.18: TP103.1@-30.875,26.875 -30.862,26.875 -30.324,27.413 -28.687,27.413 U102.38@-28.575,27.525 -28.574,27.524 v1(-27.739,27.522) v1(-27.739,27.522)
  Siganl4 w0.18: v1(-28.311,43.076) -28.281,43.106 -26.019,43.106 ; v1(-27.739,27.522) -27.739,27.911 -25.242,30.408 -25.242,41.953 -26.019,42.729 -26.019,43.106 ; v1(-7.505,40.336) -8.929,40.336 -13.518,44.925 -24.779,44.925 -26.019,43.685 -26.019,43.106
  Bottom Layer w0.18: R200.1@-28.346,42.713 R200.1@-28.308,42.751 ; v1(-28.311,43.076) v1@-28.308,43.074 ; CON201.3@-27.231,44.52 CON201.3@-27.25,44.501 -27.25,43.675 -27.45,43.475 -28.119,43.475 -28.269,43.325 -28.269,43.113 v1@-28.308,43.074 ; U400.19@-7.8,39.4 -7.8,40.025 -7.525,40.3 R403.1@-7.225,40.6 ; R200.1@-28.308,42.751 v1@-28.308,43.074 ; R200.1@-28.308,42.751 -28.308,42.703 R200.1@-28.306,42.701 -28.306,42.748 R200.1@-28.308,42.751
I2C1_SCL: CON200.18 P200.2 R120.1 U102.57 | length 41.1
  Top Layer w0.18: U102.57@-14.512,26.538 -13.829,26.538 v1(-13.499,26.209)
  Siganl4 w0.18: v1@-21.26,7.625 -17.313,7.625 -12.427,12.512 -12.427,25.484 -13.151,26.208 v1@-13.498,26.208
  Bottom Layer w0.18: CON200.18@-26.389,6.092 -26.389,7.573 -25.892,8.071 -21.705,8.071 v1(-21.268,7.633) ; R120.1@-22.876,8.071 R120.1@-22.86,8.087 ; v1(-13.499,26.209) -13.457,26.251 -13.302,26.251 -13.286,26.266 -11.155,26.266 -9.111,24.223 ; P200.2@-8.25,23.86 -8.661,23.86 -9.024,24.223 -9.111,24.223 ; P200.2@-8.207,23.141 -8.207,23.319 -9.111,24.223
I2C1_SDA: CON200.17 P200.1 U102.66 | length 44.6
  Top Layer w0.18: v1(-24.15,29.485) -24.113,29.523 -24.113,30.287 U102.66@-24.075,30.325
  Siganl4 w0.18: v1(-25.856,7.21) -25.926,7.28 -25.926,13.934 -24.79,15.069 -24.79,19.443 -24.862,19.515 -24.862,19.644 -25.778,20.56 -25.778,27.504 -24.157,29.126 v1@-24.157,29.479
  Bottom Layer w0.18: CON200.17@-25.892,6.095 -25.892,7.173 v1(-25.856,7.21) ; v1(-24.82,19.473) -24.284,20.008 -15.908,20.008 -15.151,19.251 -8.907,19.251 -8.25,19.908 P200.1@-8.25,21.32
KEY_BOOT: C300.2 D300.K K300.1 K300.2 TP300.1 U102.82 | length 20.9
  Top Layer w0.18: K300.2@-22.5,39.275 -22.45,39.325 C300.2@-15.7,39.325 ; K300.1@-18.1,39.275 -17.937,39.275 -17.677,39.015 v1(-17.677,38.678) ; U102.82@-17.475,28.525 -17.475,28.367 -17.006,27.898 -17.006,27.788 v1(-16.964,27.746)
  Siganl4 w0.18: v1(-17.677,38.678) -17.677,38.619 -17.55,38.491 -17.55,28.332 v1(-16.964,27.746)
  Bottom Layer w0.18: TP300.1@-17.688,39.626 -17.683,39.621 -17.683,38.683 v1(-17.677,38.678)
KEY_USER0: C303.2 D303.K K303.3 TP303.1 U102.5 | length 26.7
  Top Layer w0.18: U102.5@-22.675,18.142 -22.633,18.184 -22.633,19.073 v1(-22.59,19.115) ; v1@-6.354,18.501 -4.2,16.347 D303.K@-4.2,12.725 -2.625,12.725 K303.3@-2.575,12.775
  Bottom Layer w0.18: v1@-22.59,19.102 -21.994,18.506 -6.423,18.506 v1(-6.386,18.469) ; v1(-3.426,12.714) -3.4,12.688 -3.4,11.833 TP303.1@-3.374,11.807
KEY_USER1: C304.2 D304.K K304.3 TP304.1 U102.19 | length 13.1
  Top Layer w0.18: U102.19@-12.375,26.425 -10.648,26.425 -9.441,25.219 -5.269,25.219 -4.175,24.125 C304.2@-4.175,23.65 D304.K@-4.175,22.725 ; D304.K@-4.15,22.725 -4.143,22.718 -2.607,22.718 K304.3@-2.575,22.75
  Bottom Layer w0.18: v1(-3.433,22.718) -3.413,22.698 -3.413,21.825 TP304.1@-3.393,21.805
KEY_USER2: C305.2 D305.K K305.3 TP305.1 U102.87 | length 27.1
  Top Layer w0.18: U102.87@-23.475,28.525 -23.475,29.22 -23.14,29.555 -22.238,29.555 v1(-22.222,29.539) ; v1(-10.719,30.242) -10.677,30.284 -10.535,30.284 -10.504,30.315 -5.56,30.315 -4.1,31.775 D305.K@-4.1,32.7 ; D305.K@-4.125,32.7 D305.K@-4.1,32.7 ; C305.2@-4.1,33.6 D305.K@-4.1,32.7 ; K305.3@-2.575,32.725 -2.588,32.712 v1(-3.461,32.712) -4.088,32.712 D305.K@-4.1,32.7
  Bottom Layer w0.18: v1(-22.222,29.539) -22.18,29.581 -22.18,29.941 -21.373,30.748 -19.236,30.748 -17.46,28.972 -14.412,28.972 -13.142,30.242 v1(-10.719,30.242) ; v1(-3.461,32.712) -3.419,32.67 -3.419,31.875 TP305.1@-3.374,31.83
LCD_CLK: C203.2 CON200.6 R117.1 | length 2.9
  Top Layer w0.18: v1(-20.375,5.075) -20.364,5.064 C203.2@-20.364,4.527
  Bottom Layer w0.18: R117.1@-20.383,7.467 -20.383,6.09 CON200.6@-20.385,6.088 -20.38,6.083 -20.38,5.08 v1(-20.375,5.075)
LCD_CS1: CON200.12 U102.52 | length 20.8
  Top Layer w0.18: U102.52@-16.866,20.291 -16.871,20.296 -16.871,21.056 v1(-16.866,21.061)
  Siganl4 w0.18: v1(-23.376,7.065) -21.879,8.562 -17.853,8.562 -17.442,8.973 -17.442,20.485 v1(-16.866,21.061)
  Bottom Layer w0.18: CON200.12@-23.385,6.088 -23.381,6.092 -23.381,7.06 v1(-23.376,7.065)
LCD_CS2: CON200.11 R120.2 | length 1.5
  Bottom Layer w0.18: CON200.11@-22.882,6.09 -22.882,7.515 R120.2@-22.86,7.537
LCD_D0: C207.2 CON200.1 R115.1 | length 2.9
  Top Layer w0.2: C207.2@-17.633,4.566 -17.633,4.961 v1(-17.616,4.978)
  Bottom Layer w0.2: CON200.1@-17.885,6.088 CON200.1@-17.845,6.048 ; CON200.1@-17.883,5.871 -17.883,5.388 -17.654,5.16 -17.654,5.016 v1(-17.616,4.978) ; CON200.1@-17.875,6.098 -17.875,7.425 R115.1@-17.825,7.475 R115.1@-17.8,7.475
LCD_D1: C206.2 CON200.2 R116.1 | length 3
  Top Layer w0.2: C206.2@-18.253,4.566 -18.253,5.002 v1(-18.22,5.035)
  Bottom Layer w0.2: R116.1@-18.477,7.468 -18.38,7.371 CON200.2@-18.38,6.093 ; CON200.2@-18.388,6.085 -18.388,5.257 -18.22,5.089 v1(-18.22,5.035)
LCD_D2: C205.2 CON200.3 R134.2 | length 35.6
  Top Layer w0.2: C205.2@-18.862,4.566 -18.862,4.997 v1(-18.824,5.035) ; R134.2@-9.593,31.963 -9.34,31.963 v1@-9.146,31.769 ; v1@-9.213,31.78 v1(-9.159,31.78)
  Signal3 w0.2: v1(-18.824,5.035) -18.786,5.073 -18.786,5.231 -18.463,5.554 -14.946,5.554 -9.628,10.872 -9.628,29.353 -8.604,30.376 -8.604,31.458 -8.907,31.761 v1@-9.139,31.761 ; v1@-9.163,31.761 v1@-9.139,31.761 ; v1(-9.159,31.78) v1@-9.139,31.761 ; v1@-9.12,31.742 v1@-9.139,31.761
  Bottom Layer w0.2: CON200.3@-18.888,6.06 -18.888,5.153 -18.824,5.089 v1(-18.824,5.035)
LCD_D3: C204.2 CON200.4 R133.2 | length 34.1
  Top Layer w0.2: C204.2@-19.461,4.566 -19.461,4.924 v1(-19.424,4.961) ; R133.2@-9.621,31.333 -9.361,31.333 v1@-9.2,31.172 ; v1@-9.234,31.195 v1(-9.196,31.157)
  Signal3 w0.2: v1(-19.424,4.961) -19.424,5.365 -18.546,6.244 -15.966,6.244 -10.94,11.269 -10.94,29.286 -9.195,31.031 v1@-9.195,31.186
  Bottom Layer w0.2: v1(-19.424,4.961) -19.4,4.985 -19.4,6.072 CON200.4@-19.385,6.088
LCD_LED: CON200.10 U102.103 | length 31.9
  Top Layer w0.18: U102.103@-14.475,30.325 -14.475,30.483 -14.115,30.843 -14.115,31.003 v1(-14.073,31.045)
  Siganl4 w0.18: v1(-22.135,7.372) -22.093,7.414 -22.093,7.601 -21.566,8.128 -17.355,8.128 -13.972,11.512 -13.972,23.796 -14.163,23.988 -14.163,30.895 -14.085,30.974 v1@-14.085,31.033
  Bottom Layer w0.18: CON200.10@-22.385,6.088 -22.385,7.122 v1(-22.135,7.372)
LCD_RST: CON200.13 U102.78 | length 18.9
  Top Layer w0.18: v1(-18.699,21.428) -18.687,21.44 -18.687,22.113 U102.78@-18.675,22.125
  Siganl4 w0.18: v1(-23.928,7.356) -20.38,10.904 -20.38,19.451 -19.872,19.959 -19.872,21.228 -19.521,21.579 -18.91,21.579 -18.759,21.428 v1(-18.699,21.428)
  Bottom Layer w0.18: v1(-23.928,7.356) -23.904,7.332 -23.904,6.107 CON200.13@-23.885,6.088
LCD_TE: CON200.8 U102.58 | length 29.4
  Top Layer w0.18: U102.58@-14.525,27.725 -14.511,27.739 -13.594,27.739 v1(-13.581,27.753)
  Siganl4 w0.18: v1@-21.357,7.029 -17.401,7.029 -12.067,12.363 -12.067,26.239 v1(-13.581,27.753)
  Bottom Layer w0.18: CON200.8@-21.385,6.088 -21.375,6.097 v1@-21.375,7.011
  other v1: -21.365,7.021
LDO28_EN: R127.1 U102.20 | length 14.5
  Top Layer w0.18: v1(-13.46,28.418) -13.418,28.376 -13.418,28.262 -12.935,27.779 -12.935,27.735 -12.725,27.525 U102.20@-12.375,27.525
  Siganl4 w0.18: v1@-15.825,38.025 -15.825,35 -13.548,32.723 -13.548,28.634 -13.502,28.588 -13.502,28.461 v1(-13.46,28.418)
  Bottom Layer w0.18: R127.1@-18.15,38.175 -15.975,38.175 v1@-15.825,38.025
  other v1: -15.821,38.044
LDO33_EN: Q301.G R128.1 R306.2 U102.16 | length 31.9
  Top Layer w0.18: v1(-13.204,23.091) -13.187,23.108 U102.16@-12.392,23.108
  Signal3 w0.18: v1(-13.704,38.03) -13.665,38.03 -13.056,37.421 -13.056,31.551 -12.78,31.276 -12.78,23.514 v1(-13.204,23.091)
  Siganl4 w0.18: v1(-13.204,23.091) -12.825,22.712 -12.825,16.381 -13.122,16.084 v1(-13.122,16.042)
  Bottom Layer w0.18: R128.1@-19.891,15.575 -19.748,15.718 -13.462,15.718 -13.138,16.042 v1(-13.122,16.042) ; v1(-13.704,38.03) -13.715,38.04 -13.715,38.465 R306.2@-13.725,38.475 -13.6,38.6 Q301.G@-13.6,39.2
MIC_N: C415.2 CON401.2 R413.2 R416.2 | length 6.1
  Top Layer w0.18: CON401.2@-8.971,39.104 -8.971,39.554 -8.531,39.994 -8.531,42.975 -8.724,43.168 v1(-8.724,43.228)
  Bottom Layer w0.18: C415.2@-8.85,41.575 -8.735,41.69 -8.735,42.21 R413.2@-8.775,42.25 -8.739,42.286 R416.2@-8.739,42.814 ; R416.2@-8.766,42.884 -8.766,43.186 v1(-8.724,43.228)
MIC_P: C414.2 CON401.1 R412.2 R415.1 | length 6.1
  Top Layer w0.18: v1(-8.039,43.241) -8.039,43.182 -8.142,43.078 -8.142,39.975 -7.721,39.554 CON401.1@-7.721,39.104
  Bottom Layer w0.18: R415.1@-8.1,42.85 -8.136,42.814 -8.136,42.311 R412.2@-8.1,42.275 -8.128,42.247 -8.128,41.653 C414.2@-8.05,41.575 ; R415.1@-8.044,42.856 -8.044,43.235 v1(-8.039,43.241)
NetANT100_1: ANT100.1 C108.1 C110.2 | length 1.6
  Top Layer w0.3: C108.1@-36.9,40.125 ANT100.1@-36.9,41.75
NetC107_2: C107.2 C108.2 U102.35 | length 14.7
  Top Layer w0.3: C108.2@-36.9,39.55 -36.9,38.515 ccw(c-34.36,38.515) -34.36,35.975 -29.615,35.975 cw(c-29.615,33.435) -27.075,33.435 U102.35@-27.075,32.475
NetC115_2: C115.2 U104.4 | length 1.3
  Bottom Layer w0.3: C115.2@-25.225,38.175 U104.4@-23.95,38.175
NetC116_2: C116.2 U105.4 | length 1.3
  Bottom Layer w0.3: U105.4@-17.793,14.191 C116.2@-16.493,14.191
NetC406_2: C406.2 R407.1 | length 0.6
  Bottom Layer w0.18: R407.1@-6.192,16.377 -6.191,16.377 -5.605,16.377 C406.2@-5.604,16.376
NetC407_2: C407.2 R408.1 | length 0.6
  Bottom Layer w0.18: R408.1@-6.2,17.075 -6.199,17.074 -5.612,17.074 C407.2@-5.611,17.072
